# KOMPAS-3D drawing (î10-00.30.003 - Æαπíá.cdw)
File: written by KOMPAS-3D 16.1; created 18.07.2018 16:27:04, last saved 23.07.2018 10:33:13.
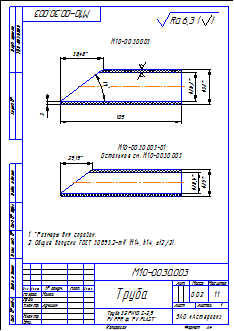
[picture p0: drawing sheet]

Sheet 1: A4, portrait

Title block, sheet 1: name: Труба; designation: М10-00.30.003; mass: 0,02; scale: 1:1; sheets: 1; organisation: ЗАО «Астерион»; sheet format: A4; stored path: Z:\Магна\Магна Ins\Магна ins 10\М10-00.00.000\3Д\М10-00.30.003 - Труба.cdw; drawn by: Милов; technical control: Лучихин

Views: Вид 1, Местный разрез 1, Спереди, Проекционный вид 2
Referenced files in Z:\1 ПКИ 3D\Полипропиленовые фитинги, трубы\Трубы\: Труба 32 PN10 S=2,9 FV PPR ф. FV PLAST.m3d
Referenced files in Z:\Магна\Магна Ins\Магна ins 10\М10-00.00.000\3Д\: М10-00.30.003 - Труба.m3d
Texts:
  Труба 32 PN10 S=2,9
  FV PPR ф. "FV PLAST"
  Остальное см.  М10-00.30.003
  *Размеры для справок.
  Общие допуски ГОСТ 30893.2-mK (H14, h14,  t2/2).
  Ra 6,3
  Ra 6,3 ( )
Dimensions and other numbers on the sheet: 26,2; 32; 109; 3; 38,48; 25; 20,4; 29,19; 1:1; 1; 0,02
